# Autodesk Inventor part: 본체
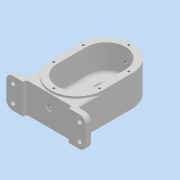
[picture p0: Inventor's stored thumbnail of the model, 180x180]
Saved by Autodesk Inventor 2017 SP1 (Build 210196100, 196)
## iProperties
Part Number: 본체
Material: 일반
Document SubType Name: Modeling
Designer: MRC
Density: 1 g/cm^3
Appearance: 기본값
Author: MRC
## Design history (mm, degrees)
sketch "스케치1"
  geometry: L1 (-40, 85)-(40, 85); L2 (40, 85)-(40, -40); L3 (40, -40)-(-40, -40); L4 (-40, -40)-(-40, 85); 2 further points
  constraints: 8 end point, 2 parallel, 1 horizontal, 1 midpoint, 1 perpendicular, 1 vertical alignment
  dimensions: "d1" = 80 distance of L1.start L1.end; "d2" = 40 distance from line of L3 point (0, 0); "d3" = 85 distance from line of L1 point (0, 0)
extrude "돌출1" new body sketch "스케치1" distance "d4" = 49; taper "d5" = 0 deg
fillet "모깎기1" dims "d6" = 40
sketch "스케치2"
  geometry: L1 (0, 45)-(0, 0); L2 (-30, 45)-(-30, 0); L3 (30, 0)-(30, 45); A1 r 30 centre (0, 45) between (30, 45) and (-30, 45); A2 r 30 centre (0, 0) between (-30, 0) and (30, 0); 2 further points
  constraints: 8 end point, 4 point on circle, 4 tangent, 2 centre point, 1 coincident, 1 midpoint, 1 parallel, 1 vertical
  dimensions: "d7" = 45 distance of L3.start L3.end; "d8" = 30 radius of A2
extrude "돌출2" cut sketch "스케치2" distance "d9" = 41; taper "d10" = 0 deg
sketch "스케치4"
  geometry: L1 (-37, -3)-(-47, -3); L2 (-47, -3)-(-47, -49); L3 (-47, -49)-(-37, -49); L4 (-37, -49)-(-37, -3); L5 (-40, 0)-(0, 0) reference
  constraints: 8 end point, 2 parallel, 1 horizontal, 1 perpendicular
  dimensions: "d11" = 10 distance of L2.end L3.end; "d12" = 46 distance of L1.end L2.end; "d13" = 3 distance between parallel lines of L1 L5; "d14" = 47 distance from line of L2 L5.end
extrude "돌출3" join sketch "스케치4" stored distance "d15" = 122; taper "d16" = 0 deg
sketch "스케치5"
  geometry: L1 (26, 5)-(96, 5); L2 (96, 5)-(96, 0); L3 (96, 0)-(26, 0); L4 (26, 0)-(26, 5); L5 (0, 0)-(122, 0) reference; 2 further points
  constraints: 8 end point, 2 midpoint, 2 parallel, 1 horizontal, 1 perpendicular, 1 vertical alignment
  dimensions: "d17" = 70 distance of L2.end L3.end; "d18" = 5 distance of L1.end L2.end
extrude "돌출4" cut sketch "스케치5" stored distance "d19" = 122; taper "d20" = 0 deg
sketch "스케치6"
  geometry: L1 (0, 45)-(0, 0); L2 (-26, 45)-(-26, 0); L3 (26, 0)-(26, 45); A1 r 26 centre (0, 45) between (26, 45) and (-26, 45); A2 r 26 centre (0, 0) between (-26, 0) and (26, 0); 2 further points
  constraints: 8 end point, 4 point on circle, 4 tangent, 2 centre point, 1 coincident, 1 midpoint, 1 parallel, 1 vertical
  dimensions: "d21" = 52 distance between parallel lines of L3 L2; "d22" = 45 distance of point (0, 0) L1.start
extrude "돌출5" join sketch "스케치6" distance "d23" = 11; taper "d24" = 0 deg
sketch "스케치7"
  geometry: L1 (-26, 15)-(26, 15); L2 (-26, 45)-(-26, 0) reference; L3 (26, 0)-(26, 45) reference; A1 r 26 centre (0, 45) between (26, 45) and (-26, 45) reference; A2 r 26 centre (0, 45) between (26, 45) and (-26, 45); 1 further point
  constraints: 4 end point, 2 point on circle, 2 point on line, 1 centre point, 1 coincident, 1 horizontal
  dimensions: "d25" = 15 distance from line of L1 point (0, 0)
extrude "돌출6" cut sketch "스케치7" distance "d26" = 3; taper "d27" = 0 deg
hole "구멍2" diameter "d39" = 22; stored, may be unused: countersink angle "d43" = 90 deg, drill point angle "d45" = 0 deg; dims "d40" = 6, "d41" = 28, "d42" = 4, "d44" = 8, "d55" = 10, "d56" = 10
hole "구멍3" diameter "d48" = 20; stored, may be unused: countersink angle "d52" = 90 deg, drill point angle "d54" = 0 deg; dims "d46" = 10, "d47" = 10, "d49" = 6, "d50" = 28, "d51" = 8, "d53" = 12
sketch "스케치8"
  geometry: C1 r 11 at (0, 45) reference; C2 r 14 at (0, 45); 1 further point
  constraints: 1 centre point, 1 coincident
  dimensions: "d57" = 28 diameter of C2
extrude "돌출7" cut sketch "스케치8" distance "d58" = 8; taper "d59" = 0 deg
node "작업 평면1"
sketch "스케치9"
  geometry: C1 r 6 at (61, 28); 1 further point
  constraints: 1 centre point, 1 vertical alignment
  dimensions: "d61" = 12 diameter of C1; "d62" = 21 distance of point (61, 49) C1.centre
extrude "돌출8" join sketch "스케치9" stored distance "d63" = 8; taper "d64" = 0 deg
hole "구멍4" diameter "d67" = 4.917; stored, may be unused: countersink angle "d71" = 90 deg, drill point angle "d73" = 0 deg; dims "d65" = 10, "d66" = 10, "d68" = 12, "d69" = 28, "d70" = 8, "d72" = 17.1
sketch "스케치10"
  geometry: C1 r 2.458 at (35, -18) reference; C2 r 6 at (35, -18); 1 further point
  constraints: 1 centre point, 1 coincident
  dimensions: "d74" = 12 diameter of C2
extrude "돌출9" cut sketch "스케치10" distance "d75" = 1; taper "d76" = 0 deg
fillet "모깎기2" dims "d77" = 10
fillet "모깎기4" dims "d86" = 3
fillet "모깎기5" dims "d87" = 3
sketch "스케치13"
  geometry: C1 r 14 at (0, 45) reference; 2 further points
  constraints: 1 vertical alignment
  dimensions: "d88" = 20 distance of point (0, 65) C1.centre
hole "구멍6" sketch "스케치13" at (0, 65) diameter "d89" = 3.242; stored, may be unused: countersink angle "d93" = 90 deg, drill point angle "d95" = 118 deg; dims "d90" = 8, "d91" = 11, "d92" = 2, "d94" = 10
sketch "스케치14"
  geometry: L1 (0, 45)-(0, 0); L2 (-35, 45)-(-35, 0); L3 (35, 0)-(35, 45); C1 r 11 at (0, 45) reference; C2 r 10 at (0, 0) reference; A1 r 35 centre (0, 45) between (35, 45) and (-35, 45); A2 r 35 centre (0, 0) between (-35, 0) and (35, 0); 8 further points
  constraints: 8 end point, 6 point on circle, 4 coincident, 4 tangent, 2 centre point, 1 midpoint, 1 parallel, 1 vertical
  dimensions: "d96" = 35 radius of A1
hole "구멍7" sketch "스케치14" at (0, 80), (-35, 45), (35, 45), (35, 0), (-35, 0), (0, -35) diameter "d97" = 3.242; stored, may be unused: countersink angle "d101" = 90 deg, drill point angle "d103" = 118 deg; dims "d98" = 8, "d99" = 11, "d100" = 2, "d102" = 10
sketch "스케치15"
  geometry: L1 (26, 45)-(26, 0) reference; L2 (-26, 0)-(-26, 45) reference; L3 (51, -37)-(51, -47) reference; L4 (51, -37)-(15.199, -37) reference; L5 (40, 0)-(40, 45) reference; L6 (-40, 45)-(-40, 0) reference; L7 (-15.199, -37)-(-51, -37) reference; L8 (-51, -47)-(-51, -37) reference; L9 (-35, -47)-(-51, -47) reference; L10 (-35, -47)-(-35, -45) reference; L11 (-32, -42)-(32, -42) reference; L12 (35, -45)-(35, -47) reference; L13 (51, -47)-(35, -47) reference; L14 (-40, 0)-(-40, -37); L15 (40, 0)-(40, -37); A1 r 26 centre (0, 45) between (26, 45) and (-26, 45) reference; A2 r 26 centre (0, 0) between (-26, 0) and (26, 0) reference; A3 r 40 centre (0, 0) between (15.199, -37) and (40, 0) reference; A4 r 40 centre (0, 45) between (40, 45) and (-40, 45) reference; A5 r 40 centre (0, 0) between (-40, 0) and (-15.199, -37) reference; A6 r 3 centre (-32, -45) between (-32, -42) and (-35, -45) reference; A7 r 3 centre (32, -45) between (35, -45) and (32, -42) reference; A8 r 40 centre (0, 0) between (-40, 0) and (40, 0) reference; 1 further point
  constraints: 4 end point, 3 tangent, 2 point on line, 2 vertical
extrude "돌출10" join sketch "스케치15" distance "d104" = 46; taper "d105" = 0 deg
sketch "스케치16"
  geometry: L1 (0, 46)-(0, 0) reference; L2 (11, 0)-(0, 0) reference; L3 (21, 36)-(21, 10) reference; L4 (0, 46)-(11, 46) reference; L5 (-80, 0)-(-80, 46) reference; L6 (-91, 46)-(-80, 46) reference; L7 (-101, 10)-(-101, 36) reference; L8 (-80, 0)-(-91, 0) reference; A1 r 10 centre (11, 10) between (11, 0) and (21, 10) reference; A2 r 10 centre (11, 36) between (21, 36) and (11, 46) reference; A3 r 10 centre (-91, 36) between (-91, 46) and (-101, 36) reference; A4 r 10 centre (-91, 10) between (-101, 10) and (-91, 0) reference; 1 further point
hole "구멍8" sketch "스케치16" at (11, 36), (11, 10), (-91, 36), (-91, 10) diameter "d106" = 6.6; stored, may be unused: countersink angle "d110" = 90 deg, drill point angle "d112" = 118 deg; dims "d107" = 8, "d108" = 11, "d109" = 2, "d111" = 10
chamfer "모따기1" distance "d116" = 1; stored, may be unused: second distance "d117" = 2, angle "d118" = 45 deg
fillet "모깎기6" dims "d119" = 3
fillet "모깎기7" dims "d120" = 3
fillet "모깎기8" dims "d121" = 0.3
fillet "모깎기9" dims "d122" = 5
sketch "스케치17"
  geometry: L1 (-35, -47)-(-51, -47) reference; 2 further points
  constraints: 1 vertical alignment, 1 other
  dimensions: "d123" = 12 distance from line of L1 point (0, -35)
feature "엠보싱1" sketch "스케치17" dims "d1" = 80, "d2" = 40, "d3" = 85, "d124" = 0.5, "d125" = 0
node "솔리드1"
pattern_circular "원형 패턴1" dims angle "d114" = 360 deg
node "투영된 루프1"
node "투영된 루프2"
node "투영된 루프3"
other parameters: "d60" = -135
